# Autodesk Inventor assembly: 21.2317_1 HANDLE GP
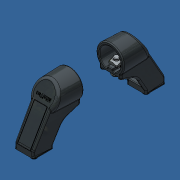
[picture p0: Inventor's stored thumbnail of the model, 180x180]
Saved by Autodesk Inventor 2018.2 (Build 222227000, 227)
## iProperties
Created: 2019-11
Part Number: 21.2317_1 HANDLE GP
Document SubType Name: Assembly
Designer: amoles
Mass: 154 g
Surface Area: 532.306 cm^2
Volume: 93.2649 cm^3
Author: amoles
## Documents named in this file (2)
- Y:\INVENTOR LIBRARIES\PARTS LIBRARY\HANDLES LOCKS STOPS\21.2317_1 HANDLE GP.iam
- Y:\INVENTOR LIBRARIES\PARTS LIBRARY\HANDLES LOCKS STOPS\21.2317_1 HANDLE GP HALF.iam
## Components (2 placed, 1 different names)
1. 21.2317_1 HANDLE GP HALF:1 [sub-assembly] — Mate:1, Mate:2, Mate:3, Flush:1
2. 21.2317_1 HANDLE GP HALF:2 [sub-assembly] — Mate:3, Flush:1
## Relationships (4: Mate 3, Flush 1)
- Mate:1: 21.2317_1 HANDLE GP HALF:1
- Mate:2: 21.2317_1 HANDLE GP HALF:1
- Mate:3: 21.2317_1 HANDLE GP HALF:1 ↔ 21.2317_1 HANDLE GP HALF:2
- Flush:1: 21.2317_1 HANDLE GP HALF:1 ↔ 21.2317_1 HANDLE GP HALF:2
